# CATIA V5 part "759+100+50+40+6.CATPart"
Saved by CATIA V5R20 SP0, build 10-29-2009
Part number: 759+100+50+40+6
Revision: TUTTO
Definition: NON CONOSCIUTO
Nomenclature: 759+100+50+40+6
Source: Unknown
Bounding box of the stored display mesh (mm): x -50 to 50, y -25 to 25, z 0 to 40
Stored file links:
  C:\Users\Utente\Desktop\IO LAVORO\3D X SITO CF\X 3D SITO CF 27-09-2020\759\759+100+50+40+6.CATPart
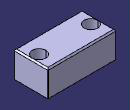
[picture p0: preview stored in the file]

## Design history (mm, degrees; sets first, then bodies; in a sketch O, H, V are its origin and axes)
Body1 "Smusso4" (main body)
  Solid1: solid without history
